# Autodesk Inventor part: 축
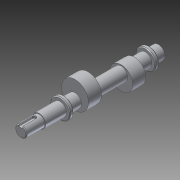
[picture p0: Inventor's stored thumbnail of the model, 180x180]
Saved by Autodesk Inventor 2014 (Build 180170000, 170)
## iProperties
Created: 2014-12
Part Number: 축
Material: 알루미늄 6061
Document SubType Name: Modeling
Designer: Owner
Mass: 170.354 g
Surface Area: 153.402 cm^2
Volume: 62.8614 cm^3
Density: 2.71 g/cm^3
Appearance: 알루미늄 - 평지
Author: Owner
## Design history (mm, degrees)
sketch "스케치1"
  geometry: L1 (-90, 0)-(90, 0); L2 (-90, 0)-(-90, 7.5); L3 (-90, 7.5)-(-66, 7.5); L4 (-66, 7.5)-(-66, 8.5); L5 (-66, 8.5)-(-39, 8.5); L6 (-39, 8.5)-(-39, 13); L7 (-39, 13)-(-34, 13); L8 (-34, 13)-(-34, 8.5); L9 (-34, 8.5)-(72, 8.5); L10 (72, 8.5)-(72, 13); L11 (72, 13)-(77, 13); L12 (77, 13)-(77, 8.5); L13 (77, 8.5)-(90, 8.5); L14 (90, 8.5)-(90, 0); 2 further points
  constraints: 28 end point, 7 parallel, 6 perpendicular, 1 coincident, 1 horizontal, 1 midpoint
  dimensions: "d0" = 180 distance of L1.start L1.end; "d1" = 15 diameter of L3 L1; "d2" = 17 diameter of L5 L1; "d3" = 24 distance of L2.end L3.end; "d5" = 26 diameter of L7 L1; "d6" = 5 distance between parallel lines of L8 L6; "d7" = 27 distance between parallel lines of L6 L4; "d9" = 17 diameter of L13 L1; "d10" = 26 diameter of L11 L1; "d11" = 13 distance between parallel lines of L14 L12; "d12" = 5 distance of L10.end L11.end; "d13" = 17 diameter of L9 L1
revolve "회전1" sketch "스케치1" stored, may be unused: angle "d14" = 90 deg
node "작업 평면1"
sketch "스케치2"
  geometry: C1 r 17.5 at (0, -6); 1 further point
  constraints: 1 centre point, 1 vertical alignment
  dimensions: "d16" = 35 diameter of C1; "d17" = 6 distance of C1.centre point (0, 0)
extrude "돌출1" join sketch "스케치2" distance "d18" = 17; taper "d19" = 0 deg
node "작업 평면2"
sketch "스케치3"
  geometry: C1 r 15 at (0, 11); 1 further point
  constraints: 1 centre point, 1 vertical alignment
  dimensions: "d21" = 30 diameter of C1; "d22" = 5 distance of C1.centre point (0, 6)
extrude "돌출2" join sketch "스케치3" distance "d23" = 17; taper "d24" = 0 deg
chamfer "모따기1" distance "d25" = 1; stored, may be unused: second distance "d26" = 2, angle "d27" = 45 deg
node "작업 평면3"
sketch "스케치4"
  geometry: L1 (7.5, -90)-(-7.5, -90) reference; L2 (-2.5, -90)-(-2.5, -72.5); L3 (2.5, -90)-(2.5, -72.5); A1 r 2.5 centre (0, -72.5) between (2.5, -72.5) and (-2.5, -72.5); 2 further points
  constraints: 4 end point, 2 point on circle, 2 point on line, 2 tangent, 1 centre point, 1 midpoint, 1 parallel, 1 perpendicular, 1 vertical alignment
  dimensions: "d31" = 5 distance between parallel lines of L3 L2; "d32" = 20 dimension on A1 L1
extrude "돌출3" cut sketch "스케치4" distance "d33" = 3; taper "d34" = 0 deg
chamfer "모따기2" distance "d35" = 1; stored, may be unused: second distance "d36" = 2, angle "d37" = 45 deg
chamfer "모따기3" distance "d38" = 1; stored, may be unused: second distance "d39" = 2, angle "d40" = 45 deg
node "솔리드1"
other parameters: "d15" = 14.5, "d20" = 43, "d28" = 7.5
